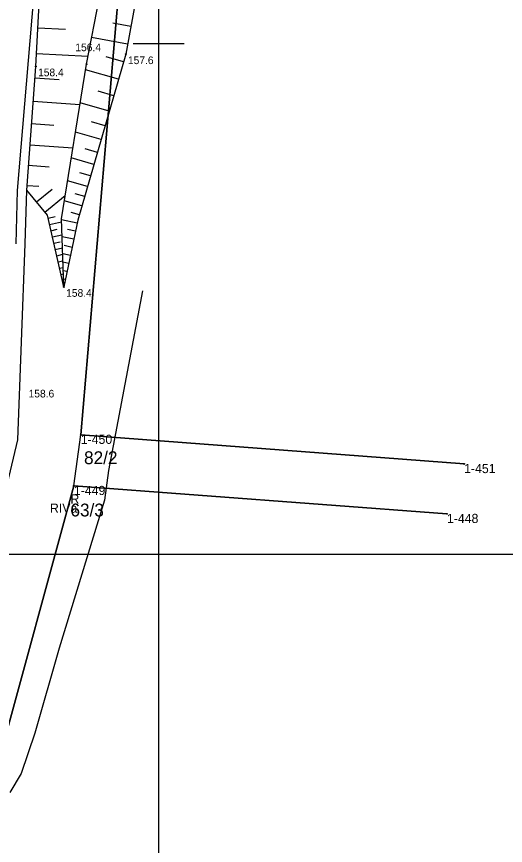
# Model space of a CAD drawing. Extents: x 5598798 to 5599616, y 5661498 to 5662453.
# Drawn here: x 5599186.1 to 5599234, y 5661721.5 to 5661802.6 of the extents above; entities that cross this region are included whole.
import ezdxf

# ---------------------------------------------------------------- set-up
doc = ezdxf.new("R2010")
doc.units = 0
for name, color, linetype in [('BUBZ_L_1', 7, 'Continuous'), ('Dzialki', 7, 'Continuous'), ('Kontury', 7, 'Continuous'), ('KTJZ_L_0', 7, 'Continuous'), ('Numery_dzialek', 7, 'Continuous'), ('Numery_konturow', 7, 'Continuous'), ('Numery_punktow', 7, 'Continuous'), ('Numery_uzytkow', 7, 'Continuous'), ('Podzial_sekcyjny_krzyze', 7, 'Continuous'), ('Podzial_sekcyjny_podstawowy', 7, 'Continuous'), ('Punkty', 7, 'Continuous'), ('RTPW_T_0', 7, 'Continuous'), ('SUPW_L_0', 7, 'Continuous'), ('Uzytki', 7, 'Continuous')]:
    doc.layers.add(name, color=color, linetype=linetype)

# ---------------------------------------------------------------- blocks, each defined once
blk = doc.blocks.new('GRO')
blk.add_circle((0, 0), 0.045)
blk = doc.blocks.new('POINT_DISPLAY')
blk.add_line((0, 0), (0, 0))
blk = doc.blocks.new('2_RTPW01')
blk.add_circle((0, 0), 0.045)

msp = doc.modelspace()

# ---------------------------------------------------------------- linework, layer by layer
at = {"layer": 'BUBZ_L_1'}
for p, q in [((5599187.97, 5661797.77), (5599188.67, 5661811.36)), ((5599198.91, 5661810.57), (5599196.77, 5661798.96)), ((5599192.92, 5661797.97), (5599194.91, 5661808.1)), ((5599188.164846, 5661801.5528), (5599190.866995, 5661801.413616)), ((5599197.272602, 5661801.686731), (5599195.524662, 5661802.008918)), ((5599196.950415, 5661799.938791), (5599193.434087, 5661800.586935)), ((5599188.03498, 5661799.031534), (5599193.077511, 5661798.771801)), ((5599196.77, 5661798.96), (5599192.09, 5661782.71)), ((5599196.550674, 5661798.198452), (5599194.853781, 5661798.687158)), ((5599187.08, 5661785.65), (5599187.97, 5661797.77)), ((5599190.47, 5661782.84), (5599192.92, 5661797.97)), ((5599196.061969, 5661796.501559), (5599192.83281, 5661797.431556)), ((5599187.887677, 5661796.648925), (5599190.268567, 5661796.47409)), ((5599195.59697, 5661794.886979), (5599194.079631, 5661795.323973)), ((5599187.720167, 5661794.367786), (5599192.282444, 5661794.032767)), ((5599195.159976, 5661793.36964), (5599192.308065, 5661794.19099)), ((5599187.559676, 5661792.18222), (5599189.745242, 5661792.021729)), ((5599194.749301, 5661791.943684), (5599193.409226, 5661792.329626)), ((5599194.363359, 5661790.603609), (5599191.844624, 5661791.329005)), ((5599187.405909, 5661790.088222), (5599191.593905, 5661789.780687)), ((5599194.000661, 5661789.344241), (5599192.817141, 5661789.685095)), ((5599193.659808, 5661788.160721), (5599191.435325, 5661788.801372)), ((5599187.258584, 5661788.081955), (5599189.264851, 5661787.934631)), ((5599193.339482, 5661787.048479), (5599192.294227, 5661787.349513)), ((5599187.113997, 5661786.112976), (5599188.26845, 5661786.028202)), ((5599193.038448, 5661786.003224), (5599191.073842, 5661786.569031)), ((5599189.1, 5661783.2), (5599187.08, 5661785.65)), ((5599188.040621, 5661784.48489), (5599189.56391, 5661785.740826)), ((5599188.857936, 5661783.493592), (5599190.840532, 5661785.128222)), ((5599192.48968, 5661784.097777), (5599190.754589, 5661784.597484)), ((5599192.755545, 5661785.02092), (5599191.832402, 5661785.286786)), ((5599190.72, 5661776.17), (5599189.1, 5661783.2)), ((5599189.171027, 5661782.89178), (5599189.850043, 5661783.048253)), ((5599192.239827, 5661783.230232), (5599191.424531, 5661783.465037)), ((5599189.311842, 5661782.280709), (5599190.480866, 5661782.5501)), ((5599190.72, 5661776.17), (5599190.47, 5661782.84)), ((5599192.027044, 5661782.409466), (5599190.473943, 5661782.73481)), ((5599192.09, 5661782.71), (5599190.72, 5661776.17)), ((5599189.452658, 5661781.669638), (5599190.063729, 5661781.810454)), ((5599189.593474, 5661781.058567), (5599190.528693, 5661781.27408)), ((5599191.861766, 5661781.620472), (5599191.072772, 5661781.785751)), ((5599189.73429, 5661780.447496), (5599190.345361, 5661780.588312)), ((5599191.696487, 5661780.831479), (5599190.536172, 5661781.074542)), ((5599189.875105, 5661779.836425), (5599190.576519, 5661779.99806)), ((5599191.531209, 5661780.042485), (5599190.742215, 5661780.207763)), ((5599190.015921, 5661779.225355), (5599190.600433, 5661779.36005)), ((5599191.36593, 5661779.253491), (5599190.598401, 5661779.414273)), ((5599190.156737, 5661778.614284), (5599190.624346, 5661778.72204)), ((5599190.297553, 5661778.003213), (5599190.64826, 5661778.08403)), ((5599191.200652, 5661778.464498), (5599190.629515, 5661778.584139)), ((5599190.438368, 5661777.392142), (5599190.672173, 5661777.44602)), ((5599191.035373, 5661777.675504), (5599190.660629, 5661777.754005)), ((5599190.579184, 5661776.781071), (5599190.696087, 5661776.80801)), ((5599190.870095, 5661776.88651), (5599190.691744, 5661776.923871))]:
    msp.add_line(p, q, dxfattribs=at)
at = {"layer": 'Dzialki'}
for p, q in [((5599202.55, 5661880.8), (5599192.37, 5661761.69)), ((5599191.7, 5661756.68), (5599192.37, 5661761.69)), ((5599192.37, 5661761.69), (5599229.91, 5661758.83)), ((5599191.7, 5661756.68), (5599182.43, 5661722.79)), ((5599228.23, 5661753.94), (5599191.7, 5661756.68))]:
    msp.add_line(p, q, dxfattribs=at)
at = {"layer": 'Kontury'}
for p, q in [((5599192.37, 5661761.69), (5599202.55, 5661880.8)), ((5599229.91, 5661758.83), (5599192.37, 5661761.69)), ((5599182.43, 5661722.79), (5599191.7, 5661756.68)), ((5599191.7, 5661756.68), (5599228.23, 5661753.94))]:
    msp.add_line(p, q, dxfattribs=at)
at = {"layer": 'KTJZ_L_0'}
for p, q in [((5599187.97, 5661797.77), (5599188.67, 5661811.36)), ((5599188.25, 5661810.75), (5599186.15, 5661785.6)), ((5599187.08, 5661785.65), (5599187.97, 5661797.77)), ((5599186.15, 5661785.6), (5599186.02, 5661780.39)), ((5599186.91, 5661780.4), (5599187.08, 5661785.65)), ((5599186.21, 5661761.2), (5599186.91, 5661780.4)), ((5599184.89, 5661755.66), (5599186.21, 5661761.2))]:
    msp.add_line(p, q, dxfattribs=at)
at = {"layer": 'Podzial_sekcyjny_krzyze'}
for p, q in [((5599200, 5661797.5), (5599200, 5661802.5)), ((5599197.5, 5661800), (5599202.5, 5661800)), ((5599200, 5661747.5), (5599200, 5661752.5)), ((5599197.5, 5661750), (5599202.5, 5661750))]:
    msp.add_line(p, q, dxfattribs=at)
at = {"layer": 'Podzial_sekcyjny_podstawowy'}
for p, q in [((5599200, 5661750), (5599200, 5662000)), ((5598800, 5661750), (5599200, 5661750)), ((5599200, 5661500), (5599200, 5661750)), ((5599200, 5661750), (5599600, 5661750))]:
    msp.add_line(p, q, dxfattribs=at)
at = {"layer": 'SUPW_L_0'}
for p, q in [((5599198.42, 5661775.78), (5599195.1, 5661758.18)), ((5599198.42, 5661775.78), (5599195.1, 5661758.18)), ((5599195.1, 5661758.18), (5599194.68, 5661755.27)), ((5599194.68, 5661755.27), (5599190.24, 5661740.8)), ((5599190.24, 5661740.8), (5599187.88, 5661732.46)), ((5599187.88, 5661732.46), (5599186.52, 5661728.5)), ((5599186.52, 5661728.5), (5599185.42, 5661726.64))]:
    msp.add_line(p, q, dxfattribs=at)
at = {"layer": 'Uzytki'}
for p, q in [((5599202.55, 5661880.8), (5599192.37, 5661761.69)), ((5599192.37, 5661761.69), (5599229.91, 5661758.83)), ((5599191.7, 5661756.68), (5599182.43, 5661722.79)), ((5599228.23, 5661753.94), (5599191.7, 5661756.68))]:
    msp.add_line(p, q, dxfattribs=at)

# ---------------------------------------------------------------- block references
at = {"layer": 'BUBZ_L_1'}
msp.add_blockref('POINT_DISPLAY', (5599190.72, 5661776.17), dxfattribs=at)
at = {"layer": 'Punkty'}
for p in [(5599192.37, 5661761.69), (5599229.91, 5661758.83), (5599191.7, 5661756.68), (5599228.23, 5661753.94)]:
    msp.add_blockref('GRO', p, dxfattribs=at)
at = {"layer": 'RTPW_T_0', "rotation": -3.0000000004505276e-06}
for p in [(5599196.77, 5661798.96), (5599187.97, 5661797.77), (5599192.92, 5661797.97), (5599190.72, 5661776.17)]:
    msp.add_blockref('2_RTPW01', p, dxfattribs=at)

# ---------------------------------------------------------------- texts
at = {"layer": 'Numery_dzialek'}
for s, p in [('82/2', (5599192.690864, 5661758.806154)), ('63/3', (5599191.359342, 5661753.685046))]:
    msp.add_text(s, height=1.26, dxfattribs=at).set_placement(p)
at = {"layer": 'Numery_konturow'}
msp.add_text('RIVa', height=0.9, dxfattribs=at).set_placement((5599189.355582, 5661754.045046))
at = {"layer": 'Numery_punktow'}
for s, p in [('1-450', (5599192.37, 5661760.79)), ('1-451', (5599229.91, 5661757.93)), ('1-449', (5599191.7, 5661755.78)), ('1-448', (5599228.23, 5661753.04))]:
    msp.add_text(s, height=0.9, dxfattribs=at).set_placement(p)
at = {"layer": 'Numery_uzytkow'}
msp.add_text('R', height=0.9, dxfattribs=at).set_placement((5599191.359342, 5661754.945046))
at = {"layer": 'RTPW_T_0'}
for s, p in [('156.4', (5599191.839454, 5661799.255221)), ('157.6', (5599196.99, 5661797.99)), ('158.4', (5599188.19, 5661796.8)), ('158.4', (5599190.94, 5661775.2)), ('158.6', (5599187.262023, 5661765.339385))]:
    msp.add_text(s, height=0.75, dxfattribs=at).set_placement(p)

doc.saveas('drawing.dxf')
